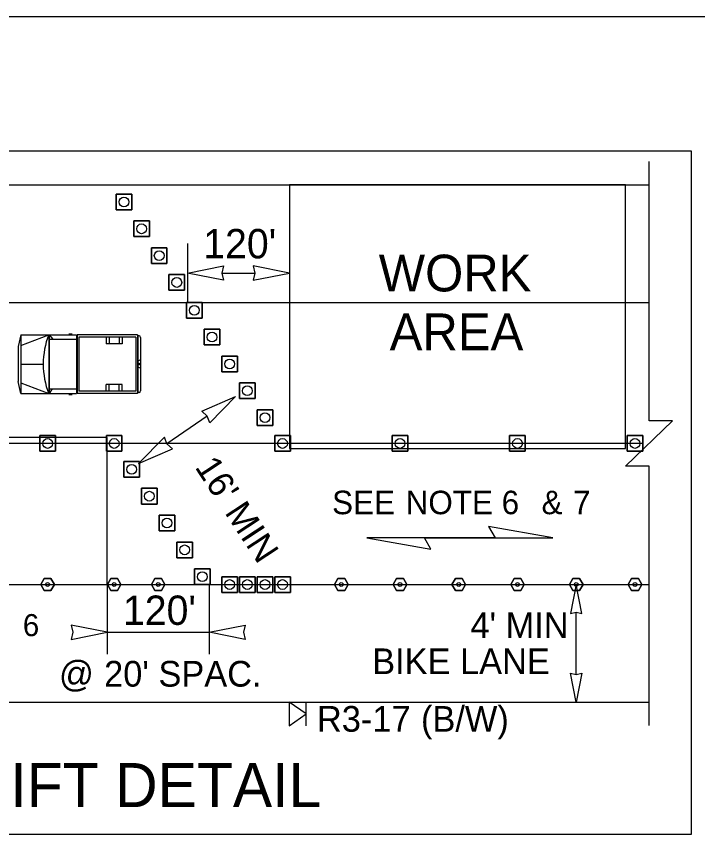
# Model space of a CAD drawing. Extents: x 99999.1 to 100095.7, y 99995 to 100010.7.
# Drawn here: x 100047.47 to 100049.325, y 100003.505 to 100005.732 of the extents above; entities that cross this region are included whole.
import ezdxf

# ---------------------------------------------------------------- set-up
doc = ezdxf.new("R2010")
doc.units = 0
for name, color, linetype in [('RD_ED_ShoulderPavedEdge', 7, 'Continuous'), ('RD_MK_LineEdgeWhite', 7, 'Continuous'), ('RD_MK_LineSkipCenter', 7, 'Continuous'), ('SH_DE_DetailHeading2Text', 7, 'Continuous'), ('SH_TI_Tables', 7, 'Continuous'), ('TR_WZ_MotoristVehicle', 7, 'Continuous'), ('TR_WZ_PortableSignMountBlk-Wht', 7, 'Continuous'), ('TR_WZ_TrafficCone', 7, 'Continuous'), ('TR_WZ_TubularMarker', 7, 'Continuous'), ('TR_WZ_WorkAreaLabel', 7, 'Continuous'), ('TR_WZ_WorkZoneDetails', 7, 'Continuous'), ('TR_WZ_WorkZoneTextCurrent', 7, 'Continuous')]:
    doc.layers.add(name, color=color, linetype=linetype)

msp = doc.modelspace()

# ---------------------------------------------------------------- linework, layer by layer
at = {"layer": 'RD_ED_ShoulderPavedEdge'}
for p, q in [((100040.1076, 100005.7323), (100055.6424, 100005.7323)), ((100045.2759, 100005.2735), (100049.1933, 100005.2735)), ((100045.2759, 100003.8655), (100049.1933, 100003.8655))]:
    msp.add_line(p, q, dxfattribs=at)
at = {"layer": 'RD_MK_LineEdgeWhite'}
for p, q in [((100045.2759, 100004.9535), (100049.1933, 100004.9535)), ((100045.2759, 100004.1855), (100049.1933, 100004.1855))]:
    msp.add_line(p, q, dxfattribs=at)
at = {"layer": 'RD_MK_LineSkipCenter'}
msp.add_lwpolyline([(100049.1767, 100004.5695), (100045.2594, 100004.5695)], dxfattribs=at)
at = {"layer": 'SH_TI_Tables'}
msp.add_lwpolyline([(100045.1619, 100005.3662), (100049.3073, 100005.3662), (100049.3073, 100003.5045), (100045.1619, 100003.5045)], close=True, dxfattribs=at)
at = {"layer": 'TR_WZ_MotoristVehicle'}
for p, q in [((100047.482, 100004.8655), (100047.4746, 100004.8332)), ((100047.482, 100004.8655), (100047.482, 100004.7055)), ((100047.482, 100004.8655), (100047.6331, 100004.8655)), ((100047.482, 100004.8362), (100047.5576, 100004.8655)), ((100047.5576, 100004.8655), (100047.5576, 100004.7055)), ((100047.559, 100004.8655), (100047.559, 100004.7055)), ((100047.559, 100004.8655), (100047.5686, 100004.8531)), ((100047.6125, 100004.8677), (100047.6216, 100004.8677)), ((100047.6331, 100004.8655), (100047.6331, 100004.7055)), ((100047.7999, 100004.8655), (100047.6353, 100004.8655)), ((100047.6353, 100004.8655), (100047.6353, 100004.7055)), ((100047.7952, 100004.8591), (100047.64, 100004.8591)), ((100047.64, 100004.8591), (100047.64, 100004.7119)), ((100047.7142, 100004.8591), (100047.7142, 100004.8407)), ((100047.7222, 100004.8591), (100047.7222, 100004.8407)), ((100047.7494, 100004.8591), (100047.7494, 100004.8407)), ((100047.7582, 100004.8591), (100047.7582, 100004.8407)), ((100047.7952, 100004.8591), (100047.7952, 100004.7119)), ((100047.7999, 100004.8655), (100047.7999, 100004.7055)), ((100047.804, 100004.8629), (100047.8005, 100004.8629)), ((100047.8005, 100004.8629), (100047.8005, 100004.7081)), ((100047.8076, 100004.858), (100047.8076, 100004.713)), ((100047.559, 100004.8531), (100047.6331, 100004.8531)), ((100047.7582, 100004.8407), (100047.7142, 100004.8407)), ((100047.4746, 100004.8332), (100047.4746, 100004.7378)), ((100047.8076, 100004.7968), (100047.8005, 100004.7938)), ((100047.482, 100004.7855), (100047.5427, 100004.7855)), ((100047.8076, 100004.7742), (100047.8005, 100004.7772)), ((100047.8057, 100004.7855), (100047.8024, 100004.7855)), ((100047.804, 100004.7877), (100047.804, 100004.7832)), ((100047.482, 100004.7055), (100047.4746, 100004.7378)), ((100047.482, 100004.7348), (100047.5576, 100004.7055)), ((100047.7142, 100004.7119), (100047.7142, 100004.7303)), ((100047.7582, 100004.7303), (100047.7142, 100004.7303)), ((100047.7222, 100004.7119), (100047.7222, 100004.7303)), ((100047.7494, 100004.7119), (100047.7494, 100004.7303)), ((100047.7582, 100004.7119), (100047.7582, 100004.7303)), ((100047.482, 100004.7055), (100047.6331, 100004.7055)), ((100047.559, 100004.7179), (100047.6331, 100004.7179)), ((100047.5669, 100004.7179), (100047.559, 100004.7055)), ((100047.6125, 100004.7032), (100047.6216, 100004.7032)), ((100047.7999, 100004.7055), (100047.6353, 100004.7055)), ((100047.7952, 100004.7119), (100047.64, 100004.7119)), ((100047.804, 100004.7081), (100047.8005, 100004.7081))]:
    msp.add_line(p, q, dxfattribs=at)
for centre, major_axis, start_param, end_param in [((100047.6656, 100004.7855), (0, -0.1679), 4.215667, 5.208926), ((100047.804, 100004.858), (0, 0.00488), 4.712389, 6.283185), ((100047.804, 100004.713), (0, -0.00488), 0, 1.570796)]:
    msp.add_ellipse(centre, major_axis=major_axis, ratio=0.73155, start_param=start_param, end_param=end_param, dxfattribs=at)
msp.add_ellipse((100047.804, 100004.7855), major_axis=(0, 0.00225), ratio=0.73155, dxfattribs=at)
at = {"layer": 'TR_WZ_PortableSignMountBlk-Wht'}
msp.add_line((100048.2589, 100003.8011), (100048.2589, 100003.8655), dxfattribs=at)
msp.add_lwpolyline([(100048.2589, 100003.8333), (100048.2127, 100003.8655), (100048.2127, 100003.8011)], close=True, dxfattribs=at)
at = {"layer": 'TR_WZ_TrafficCone'}
for points in [[(100047.7413, 100005.2484), (100047.7839, 100005.2484), (100047.7839, 100005.2058), (100047.7413, 100005.2058), (100047.7413, 100005.2484)], [(100047.7413, 100005.2058), (100047.7839, 100005.2058), (100047.7839, 100005.2484), (100047.7413, 100005.2484), (100047.7413, 100005.2058)], [(100047.7893, 100005.1754), (100047.8319, 100005.1754), (100047.8319, 100005.1327), (100047.7893, 100005.1327), (100047.7893, 100005.1754)], [(100047.7893, 100005.1327), (100047.8319, 100005.1327), (100047.8319, 100005.1754), (100047.7893, 100005.1754), (100047.7893, 100005.1327)], [(100047.8373, 100005.1023), (100047.8799, 100005.1023), (100047.8799, 100005.0596), (100047.8373, 100005.0596), (100047.8373, 100005.1023)], [(100047.8373, 100005.0596), (100047.8799, 100005.0596), (100047.8799, 100005.1023), (100047.8373, 100005.1023), (100047.8373, 100005.0596)], [(100047.8853, 100005.0292), (100047.9279, 100005.0292), (100047.9279, 100004.9866), (100047.8853, 100004.9866), (100047.8853, 100005.0292)], [(100047.8853, 100004.9866), (100047.9279, 100004.9866), (100047.9279, 100005.0292), (100047.8853, 100005.0292), (100047.8853, 100004.9866)], [(100047.9333, 100004.9535), (100047.976, 100004.9535), (100047.976, 100004.9108), (100047.9333, 100004.9108), (100047.9333, 100004.9535)], [(100047.9333, 100004.9108), (100047.976, 100004.9108), (100047.976, 100004.9535), (100047.9333, 100004.9535), (100047.9333, 100004.9108)], [(100047.9813, 100004.8804), (100048.024, 100004.8804), (100048.024, 100004.8378), (100047.9813, 100004.8378), (100047.9813, 100004.8804)], [(100047.9813, 100004.8378), (100048.024, 100004.8378), (100048.024, 100004.8804), (100047.9813, 100004.8804), (100047.9813, 100004.8378)], [(100048.0293, 100004.8074), (100048.072, 100004.8074), (100048.072, 100004.7647), (100048.0293, 100004.7647), (100048.0293, 100004.8074)], [(100048.0293, 100004.7647), (100048.072, 100004.7647), (100048.072, 100004.8074), (100048.0293, 100004.8074), (100048.0293, 100004.7647)], [(100048.0773, 100004.7343), (100048.12, 100004.7343), (100048.12, 100004.6916), (100048.0773, 100004.6916), (100048.0773, 100004.7343)], [(100048.0773, 100004.6916), (100048.12, 100004.6916), (100048.12, 100004.7343), (100048.0773, 100004.7343), (100048.0773, 100004.6916)], [(100048.1253, 100004.6612), (100048.168, 100004.6612), (100048.168, 100004.6186), (100048.1253, 100004.6186), (100048.1253, 100004.6612)], [(100048.1253, 100004.6186), (100048.168, 100004.6186), (100048.168, 100004.6612), (100048.1253, 100004.6612), (100048.1253, 100004.6186)], [(100047.5333, 100004.5908), (100047.5759, 100004.5908), (100047.5759, 100004.5482), (100047.5333, 100004.5482), (100047.5333, 100004.5908)], [(100047.5333, 100004.5482), (100047.5759, 100004.5482), (100047.5759, 100004.5908), (100047.5333, 100004.5908), (100047.5333, 100004.5482)], [(100047.7147, 100004.5908), (100047.7573, 100004.5908), (100047.7573, 100004.5482), (100047.7147, 100004.5482), (100047.7147, 100004.5908)], [(100047.7147, 100004.5482), (100047.7573, 100004.5482), (100047.7573, 100004.5908), (100047.7147, 100004.5908), (100047.7147, 100004.5482)], [(100048.2159, 100004.5908), (100048.1732, 100004.5908), (100048.1732, 100004.5482), (100048.2159, 100004.5482), (100048.2159, 100004.5908)], [(100048.2159, 100004.5482), (100048.1732, 100004.5482), (100048.1732, 100004.5908), (100048.2159, 100004.5908), (100048.2159, 100004.5482)], [(100048.4933, 100004.5908), (100048.5359, 100004.5908), (100048.5359, 100004.5482), (100048.4933, 100004.5482), (100048.4933, 100004.5908)], [(100048.4933, 100004.5482), (100048.5359, 100004.5482), (100048.5359, 100004.5908), (100048.4933, 100004.5908), (100048.4933, 100004.5482)], [(100048.8133, 100004.5908), (100048.8559, 100004.5908), (100048.8559, 100004.5482), (100048.8133, 100004.5482), (100048.8133, 100004.5908)], [(100048.8133, 100004.5482), (100048.8559, 100004.5482), (100048.8559, 100004.5908), (100048.8133, 100004.5908), (100048.8133, 100004.5482)], [(100049.1333, 100004.5908), (100049.1759, 100004.5908), (100049.1759, 100004.5482), (100049.1333, 100004.5482), (100049.1333, 100004.5908)], [(100049.1333, 100004.5482), (100049.1759, 100004.5482), (100049.1759, 100004.5908), (100049.1333, 100004.5908), (100049.1333, 100004.5482)], [(100047.8053, 100004.4778), (100047.7626, 100004.4778), (100047.7626, 100004.5204), (100047.8053, 100004.5204), (100047.8053, 100004.4778)], [(100047.8053, 100004.5204), (100047.7626, 100004.5204), (100047.7626, 100004.4778), (100047.8053, 100004.4778), (100047.8053, 100004.5204)], [(100047.8533, 100004.4047), (100047.8106, 100004.4047), (100047.8106, 100004.4474), (100047.8533, 100004.4474), (100047.8533, 100004.4047)], [(100047.8533, 100004.4474), (100047.8106, 100004.4474), (100047.8106, 100004.4047), (100047.8533, 100004.4047), (100047.8533, 100004.4474)], [(100047.9013, 100004.3316), (100047.8586, 100004.3316), (100047.8586, 100004.3743), (100047.9013, 100004.3743), (100047.9013, 100004.3316)], [(100047.9013, 100004.3743), (100047.8586, 100004.3743), (100047.8586, 100004.3316), (100047.9013, 100004.3316), (100047.9013, 100004.3743)], [(100047.9493, 100004.2586), (100047.9066, 100004.2586), (100047.9066, 100004.3012), (100047.9493, 100004.3012), (100047.9493, 100004.2586)], [(100047.9493, 100004.3012), (100047.9066, 100004.3012), (100047.9066, 100004.2586), (100047.9493, 100004.2586), (100047.9493, 100004.3012)], [(100047.9973, 100004.1855), (100047.9546, 100004.1855), (100047.9546, 100004.2282), (100047.9973, 100004.2282), (100047.9973, 100004.1855)], [(100047.9973, 100004.2282), (100047.9546, 100004.2282), (100047.9546, 100004.1855), (100047.9973, 100004.1855), (100047.9973, 100004.2282)], [(100048.072, 100004.2068), (100048.0293, 100004.2068), (100048.0293, 100004.1642), (100048.072, 100004.1642), (100048.072, 100004.2068)], [(100048.072, 100004.1642), (100048.0293, 100004.1642), (100048.0293, 100004.2068), (100048.072, 100004.2068), (100048.072, 100004.1642)], [(100048.12, 100004.2068), (100048.0773, 100004.2068), (100048.0773, 100004.1642), (100048.12, 100004.1642), (100048.12, 100004.2068)], [(100048.12, 100004.1642), (100048.0773, 100004.1642), (100048.0773, 100004.2068), (100048.12, 100004.2068), (100048.12, 100004.1642)], [(100048.168, 100004.2068), (100048.1253, 100004.2068), (100048.1253, 100004.1642), (100048.168, 100004.1642), (100048.168, 100004.2068)], [(100048.168, 100004.1642), (100048.1253, 100004.1642), (100048.1253, 100004.2068), (100048.168, 100004.2068), (100048.168, 100004.1642)], [(100048.1732, 100004.2068), (100048.2159, 100004.2068), (100048.2159, 100004.1642), (100048.1732, 100004.1642), (100048.1732, 100004.2068)], [(100048.1732, 100004.1642), (100048.2159, 100004.1642), (100048.2159, 100004.2068), (100048.1732, 100004.2068), (100048.1732, 100004.1642)]]:
    msp.add_lwpolyline(points, dxfattribs=at)
for centre in [(100047.7626, 100005.2271), (100047.8106, 100005.154), (100047.8586, 100005.081), (100047.9066, 100005.0079), (100047.9546, 100004.9322), (100048.0026, 100004.8591), (100048.0506, 100004.786), (100048.0986, 100004.713), (100048.1466, 100004.6399), (100047.5546, 100004.5695), (100047.736, 100004.5695), (100048.1946, 100004.5695), (100048.5146, 100004.5695), (100048.8346, 100004.5695), (100049.1546, 100004.5695), (100047.7839, 100004.4991), (100047.8319, 100004.426), (100047.8799, 100004.353), (100047.9279, 100004.2799), (100047.9759, 100004.2068), (100048.0506, 100004.1855), (100048.0986, 100004.1855), (100048.1466, 100004.1855), (100048.1946, 100004.1855)]:
    msp.add_circle(centre, 0.0133, dxfattribs=at)
at = {"layer": 'TR_WZ_TubularMarker'}
for points in [[(100047.5731, 100004.1855), (100047.5638, 100004.2015), (100047.5454, 100004.2015), (100047.5361, 100004.1855), (100047.5454, 100004.1695), (100047.5638, 100004.1695)], [(100047.7545, 100004.1855), (100047.7452, 100004.2015), (100047.7268, 100004.2015), (100047.7175, 100004.1855), (100047.7268, 100004.1695), (100047.7452, 100004.1695)], [(100047.8744, 100004.1855), (100047.8652, 100004.2015), (100047.8467, 100004.2015), (100047.8375, 100004.1855), (100047.8467, 100004.1695), (100047.8652, 100004.1695)], [(100048.3361, 100004.1855), (100048.3454, 100004.2015), (100048.3639, 100004.2015), (100048.3731, 100004.1855), (100048.3639, 100004.1695), (100048.3454, 100004.1695)], [(100048.4961, 100004.1855), (100048.5054, 100004.2015), (100048.5239, 100004.2015), (100048.5331, 100004.1855), (100048.5239, 100004.1695), (100048.5054, 100004.1695)], [(100048.6561, 100004.1855), (100048.6654, 100004.2015), (100048.6839, 100004.2015), (100048.6931, 100004.1855), (100048.6839, 100004.1695), (100048.6654, 100004.1695)], [(100048.8161, 100004.1855), (100048.8254, 100004.2015), (100048.8439, 100004.2015), (100048.8531, 100004.1855), (100048.8439, 100004.1695), (100048.8254, 100004.1695)], [(100048.9761, 100004.1855), (100048.9854, 100004.2015), (100049.0039, 100004.2015), (100049.0131, 100004.1855), (100049.0039, 100004.1695), (100048.9854, 100004.1695)], [(100049.1361, 100004.1855), (100049.1454, 100004.2015), (100049.1638, 100004.2015), (100049.1731, 100004.1855), (100049.1638, 100004.1695), (100049.1454, 100004.1695)]]:
    msp.add_lwpolyline(points, close=True, dxfattribs=at)
for points in [[(100047.5638, 100004.1695), (100047.5454, 100004.1695), (100047.5361, 100004.1855), (100047.5454, 100004.2015), (100047.5638, 100004.2015), (100047.5731, 100004.1855), (100047.5638, 100004.1695)], [(100047.7452, 100004.1695), (100047.7268, 100004.1695), (100047.7175, 100004.1855), (100047.7268, 100004.2015), (100047.7452, 100004.2015), (100047.7545, 100004.1855), (100047.7452, 100004.1695)], [(100047.8652, 100004.1695), (100047.8467, 100004.1695), (100047.8375, 100004.1855), (100047.8467, 100004.2015), (100047.8652, 100004.2015), (100047.8744, 100004.1855), (100047.8652, 100004.1695)], [(100048.3454, 100004.1695), (100048.3639, 100004.1695), (100048.3731, 100004.1855), (100048.3639, 100004.2015), (100048.3454, 100004.2015), (100048.3361, 100004.1855), (100048.3454, 100004.1695)], [(100048.5054, 100004.1695), (100048.5239, 100004.1695), (100048.5331, 100004.1855), (100048.5239, 100004.2015), (100048.5054, 100004.2015), (100048.4961, 100004.1855), (100048.5054, 100004.1695)], [(100048.6654, 100004.1695), (100048.6839, 100004.1695), (100048.6931, 100004.1855), (100048.6839, 100004.2015), (100048.6654, 100004.2015), (100048.6561, 100004.1855), (100048.6654, 100004.1695)], [(100048.8254, 100004.1695), (100048.8439, 100004.1695), (100048.8531, 100004.1855), (100048.8439, 100004.2015), (100048.8254, 100004.2015), (100048.8161, 100004.1855), (100048.8254, 100004.1695)], [(100048.9854, 100004.1695), (100049.0039, 100004.1695), (100049.0131, 100004.1855), (100049.0039, 100004.2015), (100048.9854, 100004.2015), (100048.9761, 100004.1855), (100048.9854, 100004.1695)], [(100049.1454, 100004.1695), (100049.1638, 100004.1695), (100049.1731, 100004.1855), (100049.1638, 100004.2015), (100049.1454, 100004.2015), (100049.1361, 100004.1855), (100049.1454, 100004.1695)]]:
    msp.add_lwpolyline(points, dxfattribs=at)
for centre in [(100047.5546, 100004.1855), (100047.736, 100004.1855), (100047.856, 100004.1855), (100048.3546, 100004.1855), (100048.5146, 100004.1855), (100048.6746, 100004.1855), (100048.8346, 100004.1855), (100048.9946, 100004.1855), (100049.1546, 100004.1855)]:
    msp.add_circle(centre, 0.00533, dxfattribs=at)
at = {"layer": 'TR_WZ_WorkZoneDetails'}
for p, q in [((100047.9359, 100005.1135), (100047.9359, 100004.9535)), ((100048.2133, 100005.1135), (100048.2133, 100004.9535)), ((100048.0297, 100005.0335), (100048.1195, 100005.0335)), ((100047.9897, 100004.6438), (100047.8798, 100004.5682)), ((100048.581, 100004.3129), (100048.7739, 100004.3129)), ((100048.7739, 100004.3129), (100048.581, 100004.3129)), ((100047.7173, 100004.1855), (100047.7173, 100003.9955)), ((100047.9946, 100004.1855), (100047.9946, 100003.9955)), ((100048.9946, 100003.9405), (100048.9946, 100004.1105)), ((100047.7173, 100004.0555), (100047.9946, 100004.0555))]:
    msp.add_line(p, q, dxfattribs=at)
msp.add_lwpolyline([(100049.1933, 100003.8015), (100049.1933, 100004.5075), (100049.1292, 100004.5075), (100049.2573, 100004.6314), (100049.1933, 100004.6314), (100049.1933, 100005.3375)], dxfattribs=at)
for points in [[(100048.2133, 100005.2735), (100048.2133, 100004.5562), (100049.1292, 100004.5562), (100049.1292, 100005.2735)], [(100047.9359, 100005.0335), (100048.0342, 100005.0528), (100048.0297, 100005.0335), (100048.0342, 100005.0142)], [(100048.2133, 100005.0335), (100048.115, 100005.0528), (100048.1195, 100005.0335), (100048.115, 100005.0142)], [(100048.0669, 100004.697), (100047.9969, 100004.6254), (100047.9897, 100004.6438), (100047.975, 100004.6571)], [(100046.7389, 100004.5855), (100046.7389, 100004.1855), (100047.7173, 100004.1855), (100047.7173, 100004.5855)], [(100047.8026, 100004.5151), (100047.8945, 100004.5549), (100047.8798, 100004.5682), (100047.8727, 100004.5867)], [(100048.9311, 100004.3129), (100048.756, 100004.3438), (100048.7739, 100004.3129)], [(100048.4238, 100004.3129), (100048.5988, 100004.2821), (100048.581, 100004.3129)], [(100048.9946, 100004.1855), (100048.9792, 100004.1069), (100048.9946, 100004.1105), (100049.01, 100004.1069)], [(100047.7173, 100004.0555), (100047.619, 100004.0748), (100047.6236, 100004.0555), (100047.619, 100004.0362)], [(100047.9946, 100004.0555), (100048.0929, 100004.0748), (100048.0884, 100004.0555), (100048.0929, 100004.0362)], [(100048.9946, 100003.8655), (100048.9792, 100003.9441), (100048.9946, 100003.9405), (100049.01, 100003.9441)]]:
    msp.add_lwpolyline(points, close=True, dxfattribs=at)

# ---------------------------------------------------------------- texts
at = {"layer": 'SH_DE_DetailHeading2Text'}
msp.add_text('OPTIONAL LANE SHIFT DETAIL', height=0.12, rotation=360, dxfattribs=at).set_placement((100045.9105, 100003.5795))
at = {"layer": 'TR_WZ_WorkAreaLabel'}
for s, p in [('WORK', (100048.4567, 100004.9835)), ('AREA', (100048.4864, 100004.8235))]:
    msp.add_text(s, height=0.1, dxfattribs=at).set_placement(p)
at = {"layer": 'TR_WZ_WorkZoneDetails'}
for s, p in [('R3-17', (100048.2884, 100003.7847)), ('(B/W)', (100048.5718, 100003.7847))]:
    msp.add_text(s, height=0.07, dxfattribs=at).set_placement(p)
at = {"layer": 'TR_WZ_WorkZoneTextCurrent'}
for s, height, rotation, p in [("120'", 0.08, 360, (100047.9785, 100005.0735)), ("16' MIN", 0.07, 303.3023, (100047.9542, 100004.5052)), ("120'", 0.08, 360, (100047.7598, 100004.0755)), ('@', 0.07, 360, (100047.5857, 100003.9075)), ("20' SPAC.", 0.07, 360, (100047.7086, 100003.9075))]:
    msp.add_text(s, height=height, rotation=rotation, dxfattribs=at).set_placement(p)
for s, height, p in [('SEE', 0.064, (100048.3296, 100004.3769)), ('NOTE 6', 0.064, (100048.53, 100004.3769)), ('&', 0.064, (100048.9002, 100004.3769)), ('7', 0.064, (100048.9859, 100004.3769)), ('6', 0.06, (100047.4872, 100004.0449)), ("4' MIN", 0.07, (100048.7064, 100004.0395)), ('BIKE LANE', 0.07, (100048.4388, 100003.9415))]:
    msp.add_text(s, height=height, dxfattribs=at).set_placement(p)

doc.saveas('drawing.dxf')
